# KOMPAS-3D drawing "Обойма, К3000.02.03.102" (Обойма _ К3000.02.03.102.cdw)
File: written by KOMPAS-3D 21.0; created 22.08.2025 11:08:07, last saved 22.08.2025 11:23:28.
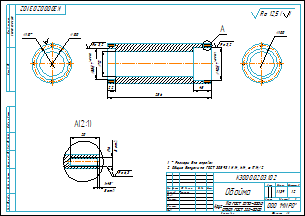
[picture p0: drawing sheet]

Sheet 1: A3, landscape

Document properties: Автор: Lutik; Знак неуказанной шероховатости: 4; Параметр неуказанной шероховатости: Ra 12,5; Масса: 11.391947

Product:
- Part/product: Обойма  | designation К3000.02.03.102
    Материал: Круг$d110 ГОСТ 2590-2006;Ст3сп ГОСТ 535-2005$ (density 7850 kg/m3)
    Масса: 11.391947

Title block, sheet 1: Наименование: Обойма; designation: К3000.02.03.102; Материал: Круг 110 ГОСТ 2590-2006 Ст3сп ГОСТ 535-2005; Масса: 11,39; Количество листов документа: 1; organisation: ООО "МИРО"; Форматы листов документа: A3; stored path: C:\Users\Lutik\YandexDisk\Документы\Новая папка\Бабка задняя\2D\Опора_К3000.02.03.000\Обойма _ К3000.02.03.102.cdw; Разработал: Тимонин

Views: Вид 1, Спереди, Проекционный вид 2, Проекционный вид 3, Выносной элемент 4, Выносной элемент А, Выносной элемент
Referenced files in C:\Users\Lutik\YandexDisk\Документы\Новая папка\Бабка задняя\3D\: Обойма.m3d
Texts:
  Ra 3,2
  Ra 6,3
  Ra 12,5
  Ra 12,5 ( )
  К3000.02.03.102 Обойма
Dimensions and other numbers on the sheet: 110; 100; 90; 85; 70; 286; 48; 22; 6; 8 отв.; 20; 1; 1:2; 11,39

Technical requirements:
  * Размеры для справок.
  Общие допуски по ГОСТ 30893.1: Н14, h14, ± IT14/2.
